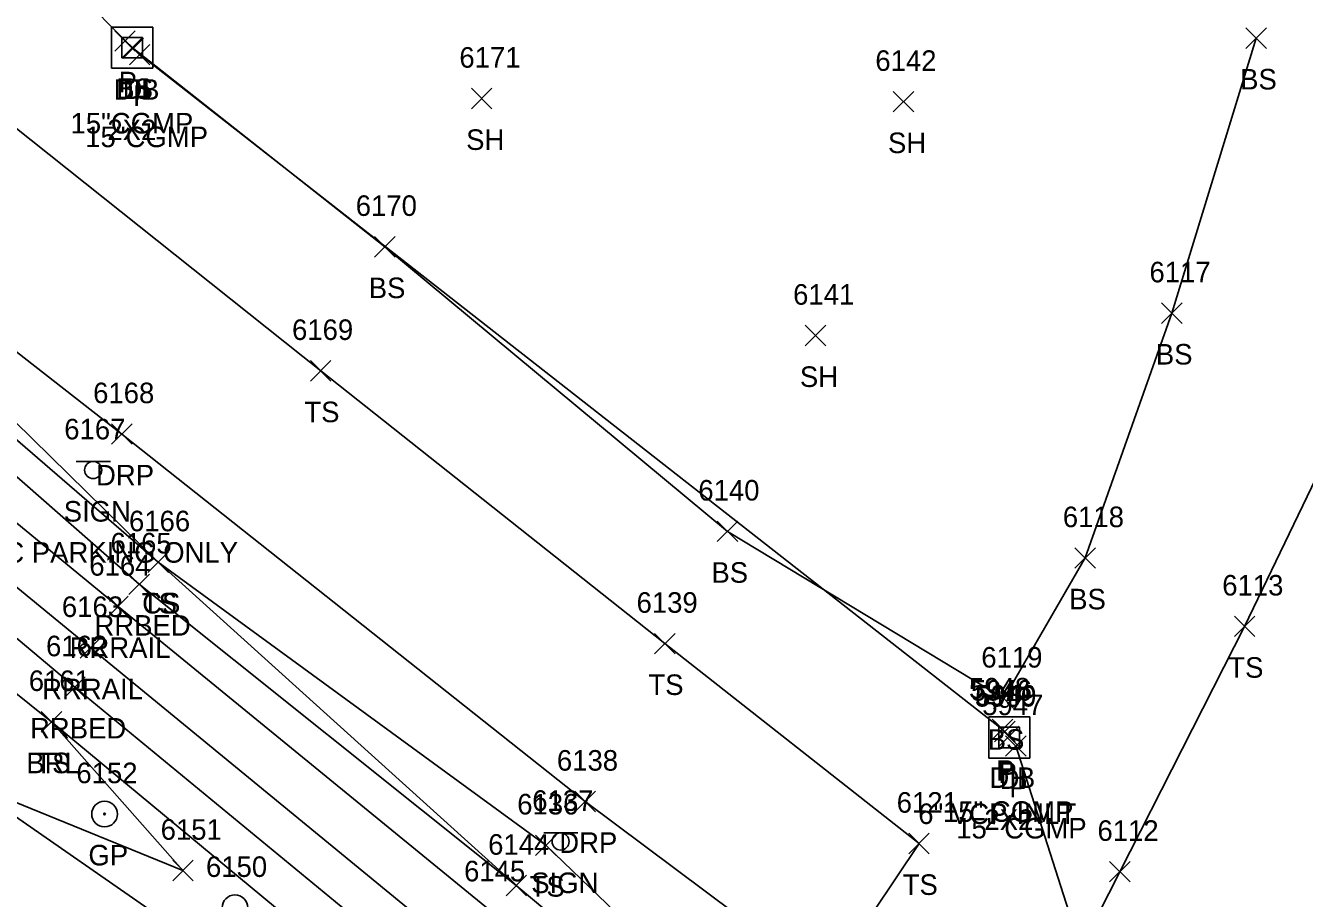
# Model space of a CAD drawing. Extents: x 1618146 to 1620418, y 640749 to 641927.
# Drawn here: x 1619881.9 to 1620006.3, y 641365.2 to 641450.1 of the extents above; entities that cross this region are included whole.
import ezdxf

# ---------------------------------------------------------------- set-up
doc = ezdxf.new("R2010")
doc.units = 0
for name, color, linetype in [('D_A', 7, 'Continuous'), ('D_C', 7, 'Continuous'), ('D_I', 7, 'Continuous'), ('D_TIC', 7, 'Continuous'), ('DCP', 7, 'Continuous'), ('DS', 7, 'Continuous'), ('L_A', 7, 'Continuous'), ('L_I', 7, 'Continuous'), ('L_TIC', 7, 'Continuous'), ('LABL', 7, 'Continuous'), ('LELB', 7, 'Continuous'), ('R_A', 7, 'Continuous'), ('R_I', 7, 'Continuous'), ('R_TIC', 7, 'Continuous'), ('RDP', 7, 'Continuous'), ('RGP', 7, 'Continuous'), ('RR', 7, 'Continuous'), ('RRB', 7, 'Continuous'), ('S_A', 7, 'Continuous'), ('S_C', 7, 'Continuous'), ('S_I', 7, 'Continuous'), ('SSGN', 7, 'Continuous')]:
    doc.layers.add(name, color=color, linetype=linetype)

msp = doc.modelspace()

# ---------------------------------------------------------------- linework, layer by layer
at = {"layer": 'D_TIC'}
for points in [[(1619890.57, 641447.64), (1619892.57, 641449.64)], [(1619892.57, 641447.64), (1619890.57, 641449.64)], [(1619891.36, 641446.92), (1619893.36, 641448.92)], [(1619893.36, 641446.92), (1619891.36, 641448.92)], [(1619892, 641446.31), (1619894, 641448.31)], [(1619894, 641446.31), (1619892, 641448.31)], [(1619975.94, 641380.67), (1619977.94, 641382.67)], [(1619977.94, 641380.67), (1619975.94, 641382.67)], [(1619976.17, 641380.46), (1619978.17, 641382.46)], [(1619978.17, 641380.46), (1619976.17, 641382.46)], [(1619976.56, 641379.97), (1619978.56, 641381.97)], [(1619978.56, 641379.97), (1619976.56, 641381.97)], [(1619977.23, 641379.05), (1619979.23, 641381.05)], [(1619979.23, 641379.05), (1619977.23, 641381.05)]]:
    msp.add_lwpolyline(points, dxfattribs=at)
at = {"layer": 'DCP'}
for points in [[(1619976.94, 641381.67), (1619893, 641447.31)], [(1619978.23, 641380.05), (1620007.4, 641288.94)]]:
    msp.add_lwpolyline(points, dxfattribs=at)
at = {"layer": 'DS'}
for p, q in [((1619890.27, 641449.99), (1619894.27, 641449.99)), ((1619890.27, 641445.99), (1619890.27, 641449.99)), ((1619894.27, 641449.99), (1619894.27, 641445.99)), ((1619891.27, 641446.99), (1619891.27, 641448.99)), ((1619891.27, 641448.99), (1619893.27, 641448.99)), ((1619893.27, 641448.99), (1619893.27, 641446.99)), ((1619893.27, 641446.99), (1619891.27, 641446.99)), ((1619892.28, 641447.99), (1619892.28, 641447.99)), ((1619892.28, 641447.99), (1619892.28, 641447.99)), ((1619894.27, 641445.99), (1619890.27, 641445.99)), ((1619975.6, 641382.88), (1619979.6, 641382.88)), ((1619975.6, 641378.88), (1619975.6, 641382.88)), ((1619979.6, 641382.88), (1619979.6, 641378.88)), ((1619976.6, 641379.88), (1619976.6, 641381.88)), ((1619976.6, 641381.88), (1619978.6, 641381.88)), ((1619978.6, 641381.88), (1619978.6, 641379.88)), ((1619978.6, 641379.88), (1619976.6, 641379.88)), ((1619977.61, 641380.88), (1619977.61, 641380.88)), ((1619977.61, 641380.88), (1619977.61, 641380.88)), ((1619979.6, 641378.88), (1619975.6, 641378.88))]:
    msp.add_line(p, q, dxfattribs=at)
at = {"layer": 'L_TIC'}
for points in [[(1620000.62, 641447.92), (1620002.62, 641449.92)], [(1620002.62, 641447.92), (1620000.62, 641449.92)], [(1619891.28, 641446.99), (1619893.28, 641448.99)], [(1619893.28, 641446.99), (1619891.28, 641448.99)], [(1619925.27, 641442.04), (1619927.27, 641444.04)], [(1619927.27, 641442.04), (1619925.27, 641444.04)], [(1619966.31, 641441.73), (1619968.31, 641443.73)], [(1619968.31, 641441.73), (1619966.31, 641443.73)], [(1619915.84, 641427.62), (1619917.84, 641429.62)], [(1619917.84, 641427.62), (1619915.84, 641429.62)], [(1619992.41, 641421.16), (1619994.41, 641423.16)], [(1619994.41, 641421.16), (1619992.41, 641423.16)], [(1619957.74, 641418.98), (1619959.74, 641420.98)], [(1619959.74, 641418.98), (1619957.74, 641420.98)], [(1619909.61, 641415.55), (1619911.61, 641417.55)], [(1619911.61, 641415.55), (1619909.61, 641417.55)], [(1619949.18, 641399.93), (1619951.18, 641401.93)], [(1619951.18, 641399.93), (1619949.18, 641401.93)], [(1619893.8, 641396.94), (1619895.8, 641398.94)], [(1619895.8, 641396.94), (1619893.8, 641398.94)], [(1619893.8, 641396.94), (1619895.8, 641398.94)], [(1619895.8, 641396.94), (1619893.8, 641398.94)], [(1619983.98, 641397.34), (1619985.98, 641399.34)], [(1619985.98, 641397.34), (1619983.98, 641399.34)], [(1619999.5, 641390.69), (1620001.5, 641392.69)], [(1620001.5, 641390.69), (1619999.5, 641392.69)], [(1619943.08, 641389.01), (1619945.08, 641391.01)], [(1619945.08, 641389.01), (1619943.08, 641391.01)], [(1619976.06, 641383.68), (1619978.06, 641385.68)], [(1619978.06, 641383.68), (1619976.06, 641385.68)], [(1619883.43, 641381.4), (1619885.43, 641383.4)], [(1619885.43, 641381.4), (1619883.43, 641383.4)], [(1619883.43, 641381.4), (1619885.43, 641383.4)], [(1619885.43, 641381.4), (1619883.43, 641383.4)], [(1619931.52, 641369.39), (1619933.52, 641371.39)], [(1619933.52, 641369.39), (1619931.52, 641371.39)], [(1619967.82, 641369.56), (1619969.82, 641371.56)], [(1619969.82, 641369.56), (1619967.82, 641371.56)], [(1619896.21, 641366.93), (1619898.21, 641368.93)], [(1619898.21, 641366.93), (1619896.21, 641368.93)], [(1619896.21, 641366.93), (1619898.21, 641368.93)], [(1619898.21, 641366.93), (1619896.21, 641368.93)], [(1619987.36, 641366.82), (1619989.36, 641368.82)], [(1619989.36, 641366.82), (1619987.36, 641368.82)], [(1619928.64, 641365.47), (1619930.64, 641367.47)], [(1619930.64, 641365.47), (1619928.64, 641367.47)]]:
    msp.add_lwpolyline(points, dxfattribs=at)
at = {"layer": 'LABL'}
for points in [[(1619897.21, 641367.93), (1619884.43, 641382.4), (1619853.25, 641407.41), (1619812.86, 641441.7), (1619772.36, 641467.89), (1619746.52, 641491.7), (1619723.5, 641512.01), (1619698.77, 641530.96), (1619675.85, 641542.41), (1619646.8, 641560.5), (1619644.52, 641553.11), (1619671.66, 641528.64)], [(1619897.21, 641367.93), (1619878.33, 641375.63), (1619848.68, 641395.56), (1619804.55, 641429.88), (1619766.28, 641459.84), (1619768.44, 641459.21), (1619730.61, 641484.73), (1619703.47, 641503.74), (1619671.66, 641528.64)]]:
    msp.add_lwpolyline(points, dxfattribs=at)
at = {"layer": 'LELB'}
for points in [[(1619959.82, 641357.09), (1619968.82, 641370.56), (1619944.08, 641390.01), (1619910.61, 641416.55), (1619871.74, 641447.47), (1619859.45, 641460.52), (1619829.4, 641492.07), (1619805.61, 641511.37), (1619797.78, 641518.22), (1619768.87, 641541.03), (1619773.26, 641565.04), (1619780.17, 641589.77), (1619783.72, 641603.58), (1619764.68, 641610.3)], [(1620001.62, 641448.92), (1619993.41, 641422.16), (1619984.98, 641398.34), (1619977.06, 641384.68), (1619950.18, 641400.93), (1619916.84, 641428.62), (1619892.28, 641447.99), (1619869.79, 641470.62), (1619837.68, 641499.78), (1619817.4, 641519.66), (1619791.65, 641544.13), (1619796.59, 641561.17), (1619804.29, 641584.54), (1619783.72, 641603.58)], [(1619929.64, 641366.47), (1619894.8, 641397.94), (1619868.57, 641423.65), (1619828.01, 641458.47), (1619808.92, 641473.07), (1619789.7, 641486.49), (1619758.41, 641511.46), (1619744.56, 641524.05), (1619747.43, 641531.14)], [(1619966.34, 641319.18), (1619952.77, 641322.95), (1619937.07, 641332.93), (1619914.51, 641349.83), (1619848.68, 641395.56), (1619808.65, 641436.47), (1619772.36, 641467.89)], [(1619974.99, 641328.72), (1619956.31, 641349.57), (1619948.66, 641354.86), (1619932.52, 641370.39), (1619894.8, 641397.94), (1619867.67, 641421.36), (1619823.44, 641453.76)], [(1619976.43, 641344.3), (1619988.36, 641367.82), (1620000.5, 641391.69), (1620009.63, 641410.63), (1620019.95, 641438.18)], [(1619938.91, 641338.68), (1619918.33, 641354.28), (1619884.43, 641382.4)]]:
    msp.add_lwpolyline(points, dxfattribs=at)
at = {"layer": 'R_TIC'}
for points in [[(1619890.26, 641409.4), (1619892.26, 641411.4)], [(1619892.26, 641409.4), (1619890.26, 641411.4)], [(1619891.95, 641394.78), (1619893.95, 641396.78)], [(1619893.95, 641394.78), (1619891.95, 641396.78)], [(1619889.89, 641392.62), (1619891.89, 641394.62)], [(1619891.89, 641392.62), (1619889.89, 641394.62)], [(1619887.22, 641388.6), (1619889.22, 641390.6)], [(1619889.22, 641388.6), (1619887.22, 641390.6)], [(1619885.68, 641384.78), (1619887.68, 641386.78)], [(1619887.68, 641384.78), (1619885.68, 641386.78)], [(1619935.33, 641373.65), (1619937.33, 641375.65)], [(1619937.33, 641373.65), (1619935.33, 641375.65)], [(1619928.64, 641365.47), (1619930.64, 641367.47)], [(1619930.64, 641365.47), (1619928.64, 641367.47)]]:
    msp.add_lwpolyline(points, dxfattribs=at)
at = {"layer": 'RDP'}
msp.add_lwpolyline([(1620046.29, 641425.2), (1620030.82, 641393.12), (1620022.2, 641371.36), (1620020.19, 641367.26), (1619996.2, 641331.35), (1619976.43, 641344.3), (1619959.82, 641357.09), (1619936.33, 641374.65), (1619891.26, 641410.4), (1619869.71, 641427.21), (1619819.71, 641475.11), (1619778.81, 641510.61), (1619747.43, 641531.14), (1619747.1, 641530.5), (1619739.15, 641529.24), (1619712.25, 641549.2), (1619714.56, 641555.95)], dxfattribs=at)
at = {"layer": 'RGP'}
msp.add_line((1619889.58, 641373.43), (1619889.58, 641373.43), dxfattribs=at)
for centre, radius in [((1619889.58, 641373.43), 1.25), ((1619889.58, 641373.43), 0.0833), ((1619902.27, 641364.31), 1.25)]:
    msp.add_circle(centre, radius, dxfattribs=at)
at = {"layer": 'RR'}
for points in [[(1620192.15, 641127.79), (1620168.31, 641155.99), (1620153.36, 641171.84), (1620133.44, 641191.99), (1620110.11, 641213.08), (1620101.47, 641220.64), (1620055.36, 641258.68), (1620021.94, 641286.1), (1619984.2, 641317.18), (1619946.81, 641347.8), (1619927.3, 641363.88), (1619890.89, 641393.62), (1619862.55, 641416.89)], [(1620190.75, 641121.59), (1620164.76, 641152.66), (1620149.83, 641168.39), (1620129.76, 641188.51), (1620106.88, 641209.4), (1620098.4, 641216.88), (1620053.4, 641253.96), (1620018.83, 641282.24), (1619980.56, 641313.63), (1619944.22, 641343.67), (1619924.21, 641360.05), (1619888.22, 641389.6), (1619859.16, 641413.43)]]:
    msp.add_lwpolyline(points, dxfattribs=at)
at = {"layer": 'RRB'}
for points in [[(1619986.51, 641321.42), (1619974.99, 641328.72), (1619954.79, 641347.39), (1619947.15, 641351.81), (1619929.64, 641366.47), (1619892.95, 641395.78), (1619865.64, 641419.74), (1619823.44, 641453.76), (1619786.96, 641483.75), (1619757.14, 641507.97), (1619741.95, 641521.56), (1619734, 641527.8), (1619709.51, 641546.08), (1619691.09, 641561.17), (1619661.22, 641583.46)], [(1619977.87, 641310.92), (1619966.34, 641319.18), (1619955.14, 641328.07), (1619947.13, 641336.24), (1619940.39, 641342.13), (1619921.41, 641357.17), (1619886.68, 641385.78), (1619856.81, 641410.87), (1619815.24, 641443.99), (1619779.42, 641474.24), (1619751.61, 641498.17), (1619728.14, 641518.29), (1619703.69, 641537.28), (1619683.35, 641552.45), (1619653.86, 641573.06)]]:
    msp.add_lwpolyline(points, dxfattribs=at)
at = {"layer": 'SSGN'}
for p, q in [((1619886.82, 641407.73), (1619890.15, 641407.73)), ((1619888.47, 641406.9), (1619888.47, 641406.9)), ((1619932.31, 641371.6), (1619935.64, 641371.6)), ((1619933.95, 641370.76), (1619933.95, 641370.76))]:
    msp.add_line(p, q, dxfattribs=at)
for centre in [(1619888.47, 641406.9), (1619933.95, 641370.76)]:
    msp.add_circle(centre, 0.833, dxfattribs=at)

# ---------------------------------------------------------------- texts
at = {"layer": 'D_A'}
for s, p in [('DIB', (1619890.46, 641442.92)), ('P', (1619890.95, 641443.64)), ('DI', (1619891.34, 641442.99)), ('P', (1619892.37, 641442.31)), ('P', (1619976.32, 641376.67)), ('DIB', (1619975.67, 641375.97)), ('P', (1619976.55, 641376.46)), ('DI', (1619976.66, 641375.88)), ('P', (1619977.6, 641375.05))]:
    msp.add_text(s, height=2, dxfattribs=at).set_placement(p)
at = {"layer": 'D_C'}
for s, p in [('15"CGMP', (1619886.27, 641439.64)), ('2X2', (1619889.85, 641438.99)), ('15"CGMP', (1619887.7, 641438.31)), ('6" VCP-INLT', (1619968.74, 641372.46)), ('15" CGMP', (1619971.15, 641372.67)), ('2X2', (1619975.18, 641371.88)), ('15" CGMP', (1619972.44, 641371.05))]:
    msp.add_text(s, height=2, dxfattribs=at).set_placement(p)
at = {"layer": 'D_I'}
for s, p in [('5948', (1619973.68, 641384.67)), ('5946', (1619973.86, 641384.46)), ('5950', (1619974.26, 641383.88)), ('5949', (1619974.3, 641383.97)), ('5947', (1619974.97, 641383.05))]:
    msp.add_text(s, height=2, dxfattribs=at).set_placement(p)
at = {"layer": 'L_A'}
for s, p in [('BS', (1620000.06, 641443.92)), ('BS', (1619890.72, 641442.99)), ('SH', (1619924.76, 641438.04)), ('SH', (1619965.8, 641437.73)), ('BS', (1619915.28, 641423.62)), ('BS', (1619991.86, 641417.16)), ('SH', (1619957.23, 641414.98)), ('TS', (1619909.02, 641411.55)), ('BS', (1619948.62, 641395.93)), ('TS', (1619893.21, 641392.94)), ('CS', (1619893.24, 641392.94)), ('BS', (1619983.43, 641393.34)), ('TS', (1619998.91, 641386.69)), ('TS', (1619942.49, 641385.01)), ('BS', (1619975.5, 641379.68)), ('BRL', (1619881.97, 641377.4)), ('TS', (1619882.84, 641377.4)), ('TS', (1619930.93, 641365.39)), ('TS', (1619967.23, 641365.56))]:
    msp.add_text(s, height=2, dxfattribs=at).set_placement(p)
at = {"layer": 'L_I'}
for s, p in [('6171', (1619924.1, 641446.04)), ('6142', (1619964.57, 641445.73)), ('6170', (1619914.02, 641431.62)), ('6117', (1619991.24, 641425.16)), ('6141', (1619956.57, 641422.98)), ('6169', (1619907.82, 641419.55)), ('6140', (1619947.35, 641403.93)), ('6166', (1619891.96, 641400.94)), ('6166', (1619891.96, 641400.94)), ('6118', (1619982.81, 641401.34)), ('6113', (1619998.32, 641394.69)), ('6139', (1619941.34, 641393.01)), ('6119', (1619974.88, 641387.68)), ('6161', (1619882.21, 641385.4)), ('6161', (1619882.21, 641385.4)), ('6136', (1619929.73, 641373.39)), ('6121', (1619966.65, 641373.56)), ('6151', (1619895.04, 641370.93)), ('6151', (1619895.04, 641370.93)), ('6112', (1619986.18, 641370.82)), ('6144', (1619926.9, 641369.47))]:
    msp.add_text(s, height=2, dxfattribs=at).set_placement(p)
at = {"layer": 'R_A'}
for s, p in [('DRP', (1619888.75, 641405.4)), ('RRBED', (1619888.6, 641390.78)), ('RRRAIL', (1619886.18, 641388.62)), ('RRRAIL', (1619883.51, 641384.6)), ('RRBED', (1619882.33, 641380.78)), ('DRP', (1619933.82, 641369.65)), ('GP', (1619888.01, 641368.43))]:
    msp.add_text(s, height=2, dxfattribs=at).set_placement(p)
at = {"layer": 'R_I'}
for s, p in [('6168', (1619888.47, 641413.4)), ('6165', (1619890.16, 641398.78)), ('6164', (1619888.1, 641396.62)), ('6163', (1619885.43, 641392.6)), ('6162', (1619883.89, 641388.78)), ('6138', (1619933.59, 641377.65)), ('6152', (1619886.84, 641376.43)), ('6144', (1619926.9, 641369.47)), ('6150', (1619899.45, 641367.31)), ('6145', (1619924.56, 641366.88))]:
    msp.add_text(s, height=2, dxfattribs=at).set_placement(p)
at = {"layer": 'S_A'}
for p in [(1619885.61, 641401.88), (1619931.09, 641365.74)]:
    msp.add_text('SIGN', height=2, dxfattribs=at).set_placement(p)
at = {"layer": 'S_C'}
msp.add_text('PUBLIC PARKING ONLY', height=2, dxfattribs=at).set_placement((1619872.1, 641397.88))
at = {"layer": 'S_I'}
for s, p in [('6167', (1619885.66, 641409.88)), ('6137', (1619931.19, 641373.74))]:
    msp.add_text(s, height=2, dxfattribs=at).set_placement(p)

doc.saveas('drawing.dxf')
